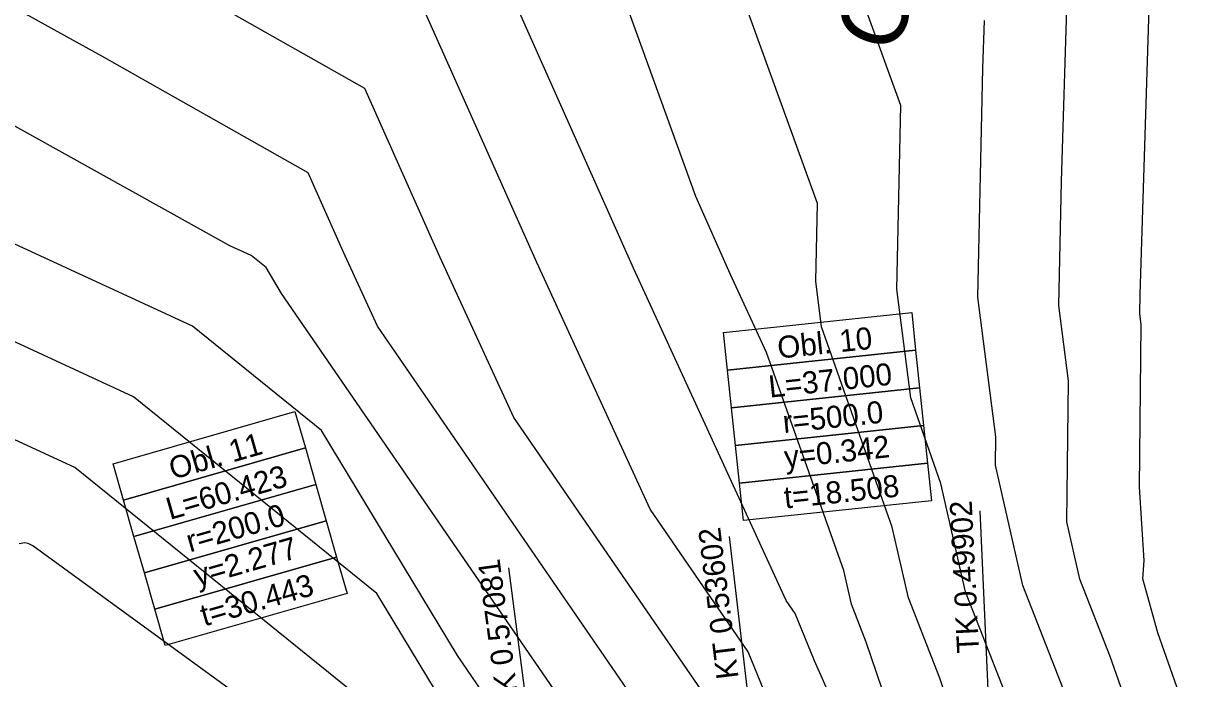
# Model space of a CAD drawing. Extents: x -549394 to -546608, y -1037055 to -1033629.
# Drawn here: x -547944.9 to -547758.4, y -1035403.9 to -1035300.1 of the extents above; entities that cross this region are included whole.
import ezdxf

# ---------------------------------------------------------------- set-up
doc = ezdxf.new("R2010")
doc.units = 0
for name, color, linetype in [('hlavni_vrst', 7, 'Continuous'), ('norm_vrst', 7, 'Continuous'), ('x_popis_oblouky_C1', 7, 'Continuous'), ('x_popis_velky_C1', 7, 'Continuous')]:
    doc.layers.add(name, color=color, linetype=linetype)

msp = doc.modelspace()

# ---------------------------------------------------------------- linework, layer by layer
at = {"layer": 'hlavni_vrst'}
for p, q in [((-547767.77, -1035343.03), (-547765.9, -1035282.86)), ((-547838.26, -1035327.5), (-547852.53, -1035288.02)), ((-547912.21, -1035335.29), (-547969.61, -1035303.43)), ((-547832.8, -1035339.75), (-547838.26, -1035327.5)), ((-547908.8, -1035336.87), (-547912.21, -1035335.29)), ((-547906.45, -1035338.77), (-547908.8, -1035336.87)), ((-547903.97, -1035342.87), (-547906.45, -1035338.77)), ((-547827.06, -1035352.23), (-547832.8, -1035339.75)), ((-547852.38, -1035417.8), (-547903.97, -1035342.87)), ((-547767.83, -1035346.02), (-547767.77, -1035343.03)), ((-547767.6, -1035347.85), (-547767.83, -1035346.02)), ((-547767.9, -1035373.6), (-547767.6, -1035347.85)), ((-547814.81, -1035386.81), (-547827.06, -1035352.23)), ((-547767.17, -1035385.18), (-547767.9, -1035373.6)), ((-547767.34, -1035388.12), (-547767.17, -1035385.18)), ((-547813.6, -1035392.13), (-547814.81, -1035386.81)), ((-547764.98, -1035396.68), (-547767.34, -1035388.12)), ((-547811.24, -1035398.16), (-547813.6, -1035392.13)), ((-547758.38, -1035415.47), (-547764.98, -1035396.68)), ((-547804.26, -1035418.77), (-547811.24, -1035398.16))]:
    msp.add_line(p, q, dxfattribs=at)
at = {"layer": 'norm_vrst'}
for p, q in [((-547890.77, -1035310.38), (-547951.66, -1035275.88)), ((-547848.15, -1035338.86), (-547872.79, -1035283.61)), ((-547932.49, -1035305.23), (-547962.88, -1035288.36)), ((-547780.25, -1035325.12), (-547779.2, -1035291.22)), ((-547818.99, -1035328.63), (-547831.8, -1035293.19)), ((-547863.51, -1035337.97), (-547881.78, -1035296.99)), ((-547805.76, -1035313.06), (-547811.08, -1035298.35)), ((-547792.74, -1035307.2), (-547792.5, -1035299.58)), ((-547899.77, -1035323.76), (-547932.49, -1035305.23)), ((-547793.55, -1035343.47), (-547792.74, -1035307.2)), ((-547878.87, -1035337.08), (-547890.77, -1035310.38)), ((-547806.41, -1035342.2), (-547805.76, -1035313.06)), ((-547894.23, -1035336.19), (-547899.77, -1035323.76)), ((-547780.69, -1035344.75), (-547780.25, -1035325.12)), ((-547819.26, -1035340.92), (-547818.99, -1035328.63)), ((-547927.45, -1035359.27), (-547982.8, -1035333.68)), ((-547918.13, -1035348.07), (-547947.78, -1035334.36)), ((-547888.78, -1035348.03), (-547894.23, -1035336.19)), ((-547867.16, -1035362.55), (-547878.87, -1035337.08)), ((-547845.54, -1035377.06), (-547863.51, -1035337.97)), ((-547823.92, -1035391.57), (-547848.15, -1035338.86)), ((-547818.33, -1035348.18), (-547819.26, -1035340.92)), ((-547804.19, -1035359.41), (-547806.41, -1035342.2)), ((-547790.7, -1035365.61), (-547793.55, -1035343.47)), ((-547779.15, -1035356.73), (-547780.69, -1035344.75)), ((-547897.66, -1035364.59), (-547918.13, -1035348.07)), ((-547844.91, -1035411.76), (-547888.78, -1035348.03)), ((-547807.1, -1035379.91), (-547818.33, -1035348.18)), ((-547936.78, -1035370.47), (-547963.45, -1035358.14)), ((-547779.41, -1035379.08), (-547779.15, -1035356.73)), ((-547888.86, -1035390.42), (-547927.45, -1035359.27)), ((-547799.38, -1035373.01), (-547804.19, -1035359.41)), ((-547837.44, -1035405.71), (-547867.16, -1035362.55)), ((-547876.1, -1035400.24), (-547897.66, -1035364.59)), ((-547790.75, -1035370.08), (-547790.7, -1035365.61)), ((-547880.07, -1035416.24), (-547936.78, -1035370.47)), ((-547786.4, -1035389.16), (-547790.75, -1035370.08)), ((-547795.47, -1035390.15), (-547799.38, -1035373.01)), ((-547829.97, -1035399.67), (-547845.54, -1035377.06)), ((-547804.54, -1035391.14), (-547807.1, -1035379.91)), ((-547777.34, -1035388.17), (-547779.41, -1035379.08)), ((-547944.7, -1035382.4), (-547945.62, -1035382.57)), ((-547944.17, -1035382.53), (-547944.7, -1035382.4)), ((-547943.43, -1035382.9), (-547944.17, -1035382.53)), ((-547880.7, -1035428.46), (-547943.43, -1035382.9)), ((-547772.54, -1035400.42), (-547777.34, -1035388.17)), ((-547776.32, -1035414.88), (-547786.4, -1035389.16)), ((-547866.89, -1035426.76), (-547888.86, -1035390.42)), ((-547822.51, -1035393.62), (-547823.92, -1035391.57)), ((-547799.55, -1035403.87), (-547804.54, -1035391.14)), ((-547787.86, -1035409.58), (-547795.47, -1035390.15)), ((-547819.45, -1035401.09), (-547822.51, -1035393.62)), ((-547859.84, -1035423.85), (-547876.1, -1035400.24)), ((-547821.93, -1035419.32), (-547829.97, -1035399.67)), ((-547816.52, -1035407.65), (-547819.45, -1035401.09)), ((-547767.3, -1035415.32), (-547772.54, -1035400.42)), ((-547794.91, -1035417.56), (-547799.55, -1035403.87))]:
    msp.add_line(p, q, dxfattribs=at)
at = {"layer": 'x_popis_oblouky_C1'}
for points in [[(-547833.87, -1035349.05), (-547804.03, -1035345.9), (-547803.41, -1035351.87), (-547833.24, -1035355.02)], [(-547833.24, -1035355.02), (-547803.41, -1035351.87), (-547802.78, -1035357.84), (-547832.61, -1035360.98)], [(-547832.61, -1035360.98), (-547802.78, -1035357.84), (-547802.15, -1035363.81), (-547831.98, -1035366.95)], [(-547930.71, -1035369.86), (-547901.87, -1035361.59), (-547900.21, -1035367.36), (-547929.05, -1035375.63)], [(-547831.98, -1035366.95), (-547802.15, -1035363.81), (-547801.52, -1035369.77), (-547831.35, -1035372.92)], [(-547929.05, -1035375.63), (-547900.21, -1035367.36), (-547898.56, -1035373.13), (-547927.4, -1035381.39)], [(-547831.35, -1035372.92), (-547801.52, -1035369.77), (-547800.89, -1035375.74), (-547830.72, -1035378.88)], [(-547927.4, -1035381.39), (-547898.56, -1035373.13), (-547896.91, -1035378.89), (-547925.74, -1035387.16)], [(-547925.74, -1035387.16), (-547896.91, -1035378.89), (-547895.25, -1035384.66), (-547924.09, -1035392.93)], [(-547924.09, -1035392.93), (-547895.25, -1035384.66), (-547893.6, -1035390.43), (-547922.44, -1035398.7)]]:
    msp.add_lwpolyline(points, close=True, dxfattribs=at)
for points in [[(-547791.34, -1035418.65), (-547793.16, -1035377.31)], [(-547828.13, -1035422.5), (-547832.95, -1035381.41)], [(-547862.57, -1035427.4), (-547867.93, -1035386.38)]]:
    msp.add_lwpolyline(points, dxfattribs=at)

# ---------------------------------------------------------------- texts
for s, rotation, p in [('Obl. 10', 6.0395, (-547825.14, -1035353.21)), ('L=37.000', 6.0395, (-547826.54, -1035359.39)), ('r=500.0', 6.0395, (-547824.3, -1035365.02)), ('Obl. 11', 16.0189, (-547921.24, -1035372.4)), ('y=0.342', 6.0395, (-547824.07, -1035370.58)), ('L=60.423', 16.0189, (-547921.69, -1035378.78)), ('t=18.508', 6.0395, (-547824.1, -1035376.97)), ('r=200.0', 16.0189, (-547918.52, -1035383.93)), ('TK 0.49902', 92.8248, (-547793.32, -1035399.79)), ('KT 0.53602', 96.9974, (-547831.48, -1035403.8)), ('y=2.277', 16.0189, (-547917.32, -1035389.37)), ('TK 0.57081', 97.7476, (-547866.16, -1035408.78)), ('t=30.443', 16.0189, (-547916.24, -1035395.67))]:
    msp.add_text(s, height=3.5, rotation=rotation, dxfattribs=at).set_placement(p)
at = {"layer": 'x_popis_velky_C1'}
msp.add_text('C1,P5/30', height=10.5, rotation=68.235, dxfattribs=at).set_placement((-547806.96, -1035305.34))

doc.saveas('drawing.dxf')
